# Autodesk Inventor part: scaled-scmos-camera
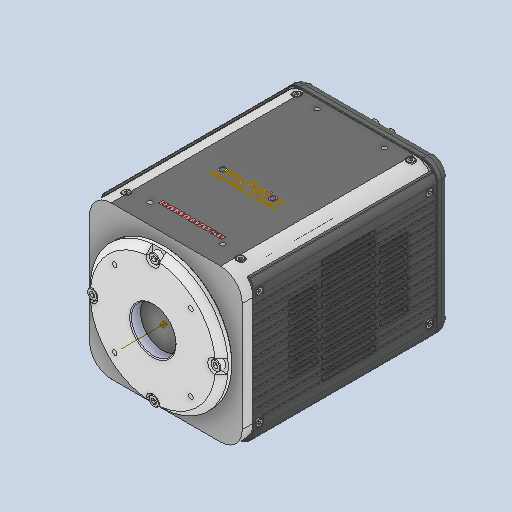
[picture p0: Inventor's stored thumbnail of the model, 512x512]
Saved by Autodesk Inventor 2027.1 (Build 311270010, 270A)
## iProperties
Created: 2026-08
Part Number: scaled-scmos-camera
Material: Generic
Document SubType Name: Modeling
Designer: dunge
Density: 1 g/cm^3
Appearance: Default
Author: dunge
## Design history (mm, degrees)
derived "B1064-10T01__C14440-20UP.ipt"
sketch "Sketch1"
  geometry: L1 (2.08, 2.4)-(62.686, 2.4); L2 (52.68, 2.4)-(56.28, 2.4) reference; L3 (62.686, 2.4)-(62.686, -64.867); L4 (62.686, -64.867)-(-4.665, -64.867); L5 (-4.665, -64.867)-(-4.665, 2.4); L6 (-4.665, 2.4)-(2.08, 2.4); A1 r 6.4 centre (2.08, -4) between (2.08, 2.4) and (-2.563, 0.405) reference; 1 further point
  constraints: 10 end point, 3 perpendicular, 1 collinear, 1 point on line
extrude "Extrusion1" join sketch "Sketch1" distance "d1" = 4.7625; taper "d2" = 0 deg
fillet "Fillet1" dims "d3" = 9.525
node "Finishes"
tag "TaggingFeature1"
body "Srf1"
body "Srf2"
body "Srf3"
body "Srf4"
body "Srf5"
body "Srf6"
body "Srf7"
body "Srf8"
body "Srf9"
body "Srf10"
body "Srf11"
body "Srf12"
body "Srf13"
body "Srf14"
body "Srf15"
body "Srf16"
body "Srf17"
body "Srf18"
body "Srf19"
body "Srf20"
body "Srf21"
body "Srf22"
body "Srf23"
body "Srf24"
body "Srf25"
body "Srf26"
body "Srf27"
body "Srf28"
workaxis "Work Axis1"
workpoint "Work Point1"
feature "Solid1::B1064-10T01__C14440-20UP.ipt"
feature "Solid2::B1064-10T01__C14440-20UP.ipt"
feature "Solid3::B1064-10T01__C14440-20UP.ipt"
feature "Solid4::B1064-10T01__C14440-20UP.ipt"
feature "Solid5::B1064-10T01__C14440-20UP.ipt"
feature "Solid6::B1064-10T01__C14440-20UP.ipt"
feature "Solid7::B1064-10T01__C14440-20UP.ipt"
feature "Solid8::B1064-10T01__C14440-20UP.ipt"
feature "Solid9::B1064-10T01__C14440-20UP.ipt"
feature "Solid10::B1064-10T01__C14440-20UP.ipt"
feature "Solid11::B1064-10T01__C14440-20UP.ipt"
feature "Solid12::B1064-10T01__C14440-20UP.ipt"
feature "Solid13::B1064-10T01__C14440-20UP.ipt"
feature "Solid14::B1064-10T01__C14440-20UP.ipt"
feature "Solid15::B1064-10T01__C14440-20UP.ipt"
feature "Solid16::B1064-10T01__C14440-20UP.ipt"
feature "Solid17::B1064-10T01__C14440-20UP.ipt"
feature "Solid18::B1064-10T01__C14440-20UP.ipt"
feature "Solid19::B1064-10T01__C14440-20UP.ipt"
feature "Solid20::B1064-10T01__C14440-20UP.ipt"
feature "Solid21::B1064-10T01__C14440-20UP.ipt"
feature "Solid22::B1064-10T01__C14440-20UP.ipt"
feature "Solid23::B1064-10T01__C14440-20UP.ipt"
feature "Solid24::B1064-10T01__C14440-20UP.ipt"
feature "Solid25::B1064-10T01__C14440-20UP.ipt"
feature "Solid26::B1064-10T01__C14440-20UP.ipt"
feature "Solid27::B1064-10T01__C14440-20UP.ipt"
feature "Solid28::B1064-10T01__C14440-20UP.ipt"
feature "Solid29::B1064-10T01__C14440-20UP.ipt"
feature "Solid30::B1064-10T01__C14440-20UP.ipt"
feature "Solid31::B1064-10T01__C14440-20UP.ipt"
feature "Solid32::B1064-10T01__C14440-20UP.ipt"
feature "Solid33::B1064-10T01__C14440-20UP.ipt"
feature "Solid34::B1064-10T01__C14440-20UP.ipt"
feature "Solid35::B1064-10T01__C14440-20UP.ipt"
feature "Solid36::B1064-10T01__C14440-20UP.ipt"
feature "Solid37::B1064-10T01__C14440-20UP.ipt"
feature "Solid38::B1064-10T01__C14440-20UP.ipt"
feature "Solid39::B1064-10T01__C14440-20UP.ipt"
feature "Solid40::B1064-10T01__C14440-20UP.ipt"
feature "Solid41::B1064-10T01__C14440-20UP.ipt"
feature "Solid42::B1064-10T01__C14440-20UP.ipt"
feature "Solid43::B1064-10T01__C14440-20UP.ipt"
feature "Solid44::B1064-10T01__C14440-20UP.ipt"
feature "Solid45::B1064-10T01__C14440-20UP.ipt"
feature "Solid46::B1064-10T01__C14440-20UP.ipt"
feature "Solid47::B1064-10T01__C14440-20UP.ipt"
feature "Solid48::B1064-10T01__C14440-20UP.ipt"
feature "Solid49::B1064-10T01__C14440-20UP.ipt"
feature "Solid50::B1064-10T01__C14440-20UP.ipt"
feature "Solid51::B1064-10T01__C14440-20UP.ipt"
feature "Solid52::B1064-10T01__C14440-20UP.ipt"
feature "Solid53::B1064-10T01__C14440-20UP.ipt"
feature "Solid54::B1064-10T01__C14440-20UP.ipt"
feature "Solid55::B1064-10T01__C14440-20UP.ipt"
feature "Solid56::B1064-10T01__C14440-20UP.ipt"
feature "Solid57::B1064-10T01__C14440-20UP.ipt"
feature "Solid58::B1064-10T01__C14440-20UP.ipt"
feature "Solid59::B1064-10T01__C14440-20UP.ipt"
feature "Solid60::B1064-10T01__C14440-20UP.ipt"
feature "Solid61::B1064-10T01__C14440-20UP.ipt"
feature "Solid62::B1064-10T01__C14440-20UP.ipt"
feature "Solid63::B1064-10T01__C14440-20UP.ipt"
feature "Solid64::B1064-10T01__C14440-20UP.ipt"
feature "Solid65::B1064-10T01__C14440-20UP.ipt"
feature "Solid66::B1064-10T01__C14440-20UP.ipt"
feature "Solid67::B1064-10T01__C14440-20UP.ipt"
feature "Solid68::B1064-10T01__C14440-20UP.ipt"
feature "Solid69::B1064-10T01__C14440-20UP.ipt"
feature "Solid70::B1064-10T01__C14440-20UP.ipt"
feature "Solid71::B1064-10T01__C14440-20UP.ipt"
feature "Solid72::B1064-10T01__C14440-20UP.ipt"
feature "Solid73::B1064-10T01__C14440-20UP.ipt"
feature "Solid74::B1064-10T01__C14440-20UP.ipt"
feature "Solid75::B1064-10T01__C14440-20UP.ipt"
feature "Solid76::B1064-10T01__C14440-20UP.ipt"
feature "Solid77::B1064-10T01__C14440-20UP.ipt"
feature "Solid78::B1064-10T01__C14440-20UP.ipt"
feature "Solid79::B1064-10T01__C14440-20UP.ipt"
feature "Solid80::B1064-10T01__C14440-20UP.ipt"
feature "Solid81::B1064-10T01__C14440-20UP.ipt"
feature "Solid82::B1064-10T01__C14440-20UP.ipt"
feature "Solid83::B1064-10T01__C14440-20UP.ipt"
feature "Solid84::B1064-10T01__C14440-20UP.ipt"
feature "Solid85::B1064-10T01__C14440-20UP.ipt"
feature "Solid86::B1064-10T01__C14440-20UP.ipt"
feature "Solid87::B1064-10T01__C14440-20UP.ipt"
feature "Solid88::B1064-10T01__C14440-20UP.ipt"
feature "Solid89::B1064-10T01__C14440-20UP.ipt"
feature "Solid90::B1064-10T01__C14440-20UP.ipt"
feature "Solid91::B1064-10T01__C14440-20UP.ipt"
feature "Solid92::B1064-10T01__C14440-20UP.ipt"
feature "Solid93::B1064-10T01__C14440-20UP.ipt"
feature "Solid94::B1064-10T01__C14440-20UP.ipt"
feature "Solid95::B1064-10T01__C14440-20UP.ipt"
feature "Solid96::B1064-10T01__C14440-20UP.ipt"
feature "Solid97::B1064-10T01__C14440-20UP.ipt"
feature "Solid98::B1064-10T01__C14440-20UP.ipt"
feature "Solid99::B1064-10T01__C14440-20UP.ipt"
feature "Solid100::B1064-10T01__C14440-20UP.ipt"
feature "Solid101::B1064-10T01__C14440-20UP.ipt"
feature "Solid102::B1064-10T01__C14440-20UP.ipt"
feature "Solid103::B1064-10T01__C14440-20UP.ipt"
feature "Solid104::B1064-10T01__C14440-20UP.ipt"
feature "Solid105::B1064-10T01__C14440-20UP.ipt"
feature "Solid106::B1064-10T01__C14440-20UP.ipt"
feature "Solid107::B1064-10T01__C14440-20UP.ipt"
feature "Solid108::B1064-10T01__C14440-20UP.ipt"
feature "Solid109::B1064-10T01__C14440-20UP.ipt"
feature "Solid110::B1064-10T01__C14440-20UP.ipt"
feature "Solid111::B1064-10T01__C14440-20UP.ipt"
feature "Solid112::B1064-10T01__C14440-20UP.ipt"
feature "Solid113::B1064-10T01__C14440-20UP.ipt"
feature "Solid114::B1064-10T01__C14440-20UP.ipt"
feature "Solid115::B1064-10T01__C14440-20UP.ipt"
feature "Solid123::B1064-10T01__C14440-20UP.ipt"
feature "Solid125::B1064-10T01__C14440-20UP.ipt"
feature "Solid146::B1064-10T01__C14440-20UP.ipt"
feature "Solid147::B1064-10T01__C14440-20UP.ipt"
feature "Solid148::B1064-10T01__C14440-20UP.ipt"
feature "Solid149::B1064-10T01__C14440-20UP.ipt"
feature "Solid150::B1064-10T01__C14440-20UP.ipt"
feature "Solid151::B1064-10T01__C14440-20UP.ipt"
feature "Solid152::B1064-10T01__C14440-20UP.ipt"
feature "Solid153::B1064-10T01__C14440-20UP.ipt"
feature "Solid154::B1064-10T01__C14440-20UP.ipt"
feature "Solid155::B1064-10T01__C14440-20UP.ipt"
feature "Solid156::B1064-10T01__C14440-20UP.ipt"
body "Solid260"
feature "Solid116::Derived"
feature "Solid117::Derived"
feature "Solid118::Derived"
feature "Solid119::Derived"
feature "Solid120::Derived"
feature "Solid121::Derived"
feature "Solid122::Derived"
feature "Solid124::Derived"
feature "Solid126::Derived"
feature "Solid127::Derived"
feature "Solid128::Derived"
feature "Solid129::Derived"
feature "Solid130::Derived"
feature "Solid131::Derived"
feature "Solid132::Derived"
feature "Solid133::Derived"
feature "Solid134::Derived"
feature "Solid135::Derived"
feature "Solid136::Derived"
feature "Solid137::Derived"
feature "Solid138::Derived"
feature "Solid139::Derived"
feature "Solid140::Derived"
feature "Solid141::Derived"
feature "Solid142::Derived"
feature "Solid143::Derived"
feature "Solid144::Derived"
feature "Solid145::Derived"
body "Solid1"
body "Solid2"
body "Solid3"
body "Solid4"
body "Solid5"
body "Solid6"
body "Solid7"
body "Solid8"
body "Solid9"
body "Solid10"
body "Solid11"
body "Solid12"
body "Solid13"
body "Solid14"
body "Solid15"
body "Solid16"
body "Solid17"
body "Solid18"
body "Solid19"
body "Solid20"
body "Solid21"
body "Solid22"
body "Solid23"
body "Solid24"
body "Solid25"
body "Solid26"
body "Solid27"
body "Solid28"
body "Solid29"
body "Solid30"
body "Solid31"
body "Solid32"
body "Solid33"
body "Solid34"
body "Solid35"
body "Solid36"
body "Solid37"
body "Solid38"
body "Solid39"
body "Solid40"
body "Solid41"
body "Solid42"
body "Solid43"
body "Solid44"
body "Solid45"
body "Solid46"
body "Solid47"
body "Solid48"
body "Solid49"
body "Solid50"
body "Solid51"
body "Solid52"
body "Solid53"
body "Solid54"
body "Solid55"
body "Solid56"
body "Solid57"
body "Solid58"
body "Solid59"
body "Solid60"
body "Solid61"
body "Solid62"
body "Solid63"
body "Solid64"
body "Solid65"
body "Solid66"
body "Solid67"
body "Solid68"
body "Solid69"
body "Solid70"
body "Solid71"
body "Solid72"
body "Solid73"
body "Solid74"
body "Solid75"
body "Solid76"
body "Solid77"
body "Solid78"
body "Solid79"
body "Solid80"
body "Solid81"
body "Solid82"
body "Solid83"
body "Solid84"
body "Solid85"
body "Solid86"
body "Solid87"
body "Solid88"
body "Solid89"
body "Solid90"
body "Solid91"
body "Solid92"
body "Solid93"
body "Solid94"
body "Solid95"
body "Solid96"
body "Solid97"
body "Solid98"
body "Solid99"
body "Solid100"
body "Solid101"
body "Solid102"
body "Solid103"
body "Solid104"
body "Solid105"
body "Solid106"
body "Solid107"
body "Solid108"
body "Solid109"
body "Solid110"
body "Solid111"
body "Solid112"
body "Solid113"
body "Solid114"
body "Solid115"
body "Solid123"
body "Solid125"
body "Solid146"
body "Solid147"
body "Solid148"
body "Solid149"
body "Solid150"
body "Solid151"
body "Solid152"
body "Solid153"
body "Solid154"
body "Solid155"
body "Solid156"
node "Finish1" dims "Finish1_Area" = 1.12778
other parameters: "d0" = 8
